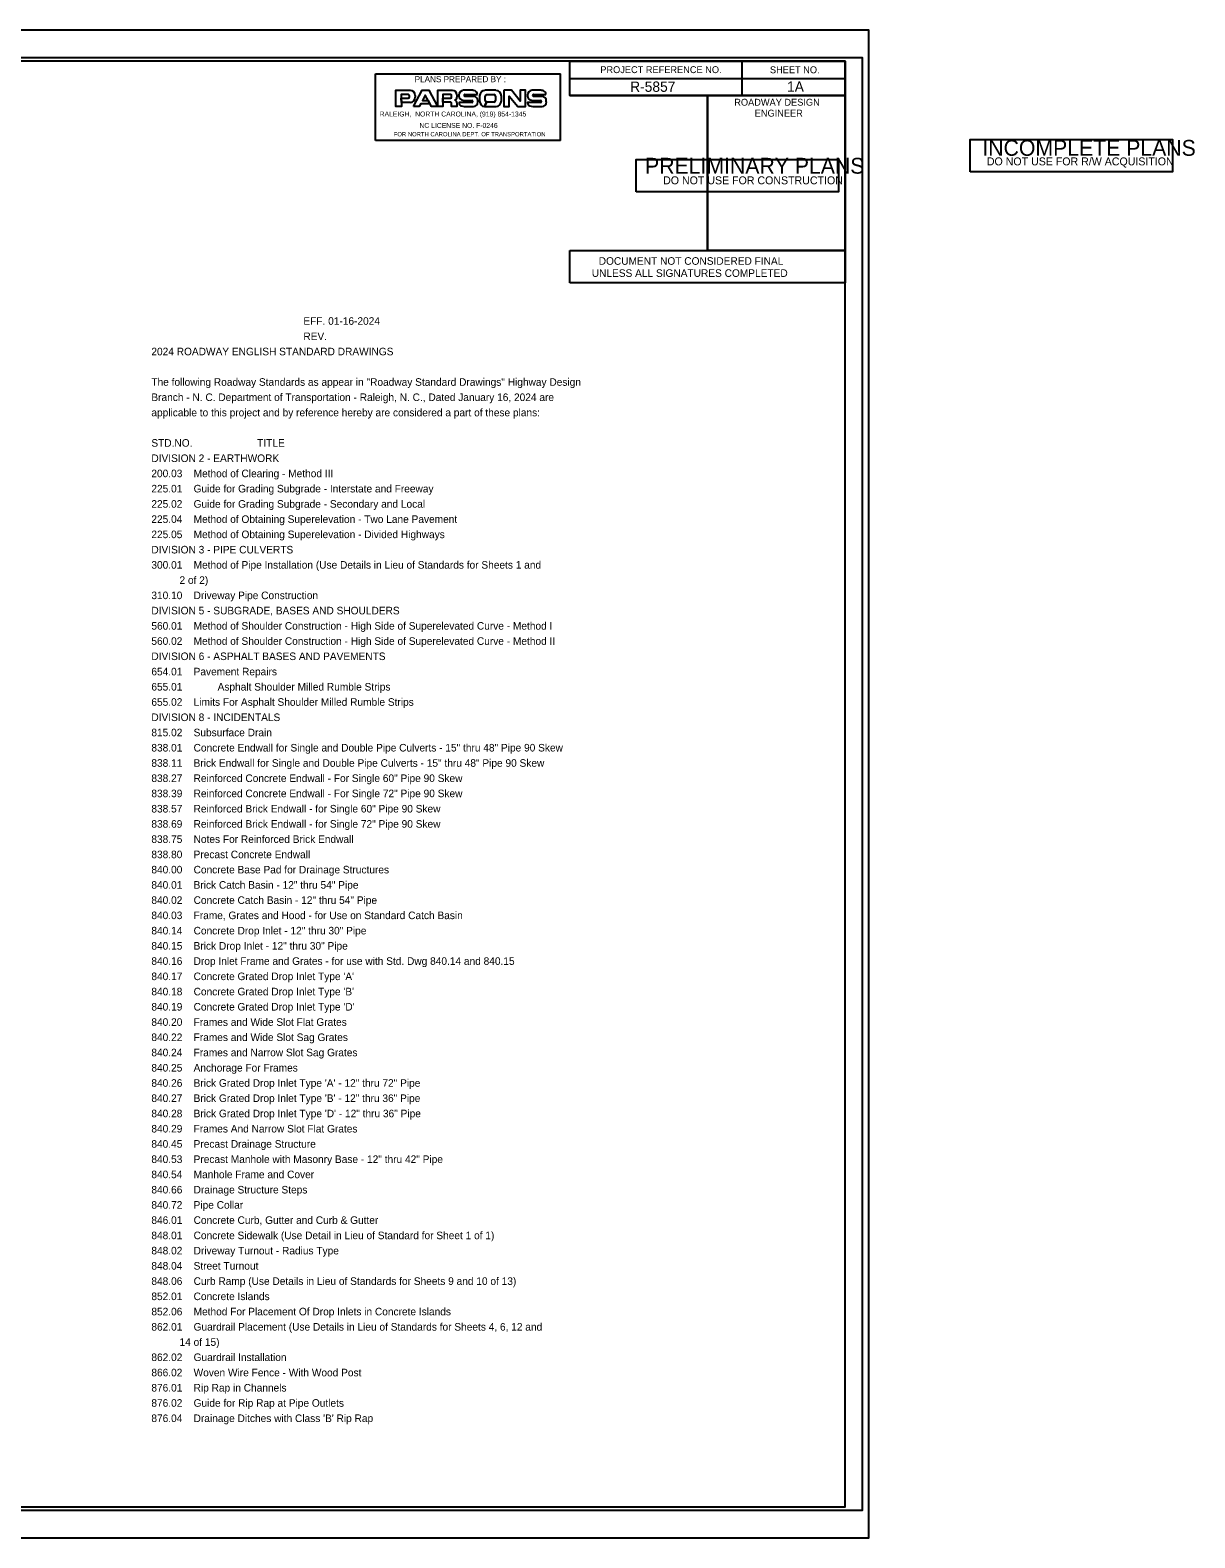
# Model space of a CAD drawing. Extents: x 779200 to 786346, y 600107 to 602297.
# Drawn here: x 782920 to 784611, y 600107 to 602297 of the extents above; entities that cross this region are included whole.
import ezdxf

# ---------------------------------------------------------------- set-up
doc = ezdxf.new("R2010")
doc.units = 0
for name, color, linetype in [('Old_Level_2', 7, 'Continuous'), ('Sheet Border Standard 30in CELL', 7, 'Continuous'), ('Sheet Cutting Line CELL', 7, 'Continuous'), ('Sheet Data Field CELL', 7, 'Continuous'), ('Sheet Plan CELL', 7, 'Continuous'), ('Sheet Plot Border Inside CELL', 7, 'Continuous'), ('Sheet Plot Border Outside CELL', 7, 'Continuous'), ('Sheet Sticker Exception Certification CELL', 7, 'Continuous'), ('Sheet Sticker Preliminary CELL', 7, 'Continuous')]:
    doc.layers.add(name, color=color, linetype=linetype)

msp = doc.modelspace()

# ---------------------------------------------------------------- linework, layer by layer
at = {"layer": 'Sheet Border Standard 30in CELL'}
for p, q in [((783953.3, 602251.6), (783953.3, 602201.6)), ((783703.2, 602226.6), (784103.3, 602226.6)), ((783703.2, 602201.6), (784103.3, 602201.6)), ((783703.2, 602201.6), (784103.3, 602201.6)), ((783903.3, 602201.6), (783903.3, 601976.7))]:
    msp.add_line(p, q, dxfattribs=at)
for points in [[(784103.3, 602251.7), (781103.3, 602251.7), (781103.3, 600151.7), (784103.3, 600151.7)], [(783703.2, 602251.7), (784103.3, 602251.7), (784103.3, 602201.6), (783703.2, 602201.6)], [(783903.3, 602201.6), (784103.3, 602201.6), (784103.3, 601976.6), (783903.3, 601976.6)]]:
    msp.add_lwpolyline(points, close=True, dxfattribs=at)
at = {"layer": 'Sheet Cutting Line CELL'}
msp.add_lwpolyline([(783799.6, 602061.9), (783799.6, 602108.9), (784093.6, 602108.9), (784093.6, 602061.9)], close=True, dxfattribs=at)
at = {"layer": 'Sheet Data Field CELL'}
msp.add_lwpolyline([(780770.3, 600106.7), (784137.3, 600106.7), (784137.3, 602296.7), (780770.3, 602296.7)], close=True, dxfattribs=at)
at = {"layer": 'Sheet Plan CELL'}
for p, q in [((783703.2, 601929.6), (783703.2, 601976.6)), ((783703.2, 601976.6), (784103.3, 601976.6)), ((784103.3, 601976.6), (784103.3, 601929.6)), ((784103.3, 601929.6), (783703.2, 601929.6))]:
    msp.add_line(p, q, dxfattribs=at)
at = {"layer": 'Sheet Plot Border Inside CELL'}
msp.add_lwpolyline([(780796.3, 600146.7), (784128.3, 600146.7), (784128.3, 602256.7), (780796.3, 602256.7)], close=True, dxfattribs=at)
at = {"layer": 'Sheet Plot Border Outside CELL'}
msp.add_lwpolyline([(784284.4, 602090.8), (784284.4, 602137.8), (784578.4, 602137.8), (784578.4, 602090.8)], close=True, dxfattribs=at)
at = {"layer": 'Sheet Sticker Exception Certification CELL'}
for p, q in [((783421.1, 602233.3), (783689.9, 602233.3)), ((783421.1, 602136.5), (783421.1, 602233.3)), ((783689.9, 602136.5), (783689.9, 602233.3)), ((783562.3, 602209.3), (783549, 602209.3)), ((783596.1, 602209.3), (783579.8, 602209.3)), ((783661.8, 602209.3), (783648.5, 602209.3)), ((783470.8, 602199.8), (783470.8, 602201.2)), ((783478.9, 602201.6), (783478.9, 602199.3)), ((783531.7, 602199.3), (783531.7, 602201.9)), ((783539.3, 602202.7), (783539.3, 602199.2)), ((783542.3, 602202.1), (783542.3, 602201.2)), ((783548.2, 602194.7), (783561.3, 602194.4)), ((783549.9, 602185.9), (783563.6, 602185.9)), ((783551.1, 602203.3), (783569.1, 602203.3)), ((783564, 602200.4), (783551.1, 602200.4)), ((783569.7, 602192.4), (783569.7, 602194.3)), ((783572.4, 602201.3), (783572.4, 602193.5)), ((783579.5, 602185.9), (783582.6, 602192.1)), ((783579.5, 602185.9), (783596.3, 602185.9)), ((783580.3, 602194.6), (783580.3, 602200.6)), ((783582.6, 602203), (783593.2, 602203)), ((783595.5, 602200.6), (783595.5, 602194.6)), ((783604, 602194.1), (783604, 602200.7)), ((783641.8, 602202.1), (783641.8, 602201.2)), ((783647.7, 602194.7), (783660.8, 602194.4)), ((783649.4, 602185.9), (783663.1, 602185.9)), ((783650.7, 602203.3), (783668.7, 602203.3)), ((783663.5, 602200.4), (783650.7, 602200.4)), ((783669.2, 602192.4), (783669.2, 602194.3)), ((783689.9, 602136.5), (783421.1, 602136.5))]:
    msp.add_line(p, q, dxfattribs=at)
for points in [[(783469, 602203), (783458.7, 602203), (783458.7, 602197.7), (783458.9, 602191.7), (783458.9, 602185.9), (783450.6, 602185.9), (783450.6, 602209.3), (783471.8, 602209.3)], [(783530.7, 602203), (783519.2, 602203), (783519.2, 602197.8), (783519.2, 602192.1), (783519.2, 602185.9), (783511.5, 602185.9), (783511.5, 602209.3), (783533.2, 602209.3)], [(783471.8, 602191.7), (783458.9, 602191.7), (783458.7, 602197.7), (783468.8, 602197.7)], [(783539.3, 602190.9), (783539.3, 602185.9), (783531.5, 602185.9), (783531.5, 602191.2), (783530.5, 602192.1), (783519.2, 602192.1), (783519.2, 602197.8), (783530.3, 602197.8)], [(783561.3, 602191.5), (783542.6, 602191.5), (783542.6, 602191.1)], [(783593.2, 602192.1), (783582.6, 602192.1), (783579.5, 602185.9), (783596.3, 602185.9)], [(783660.8, 602191.5), (783642.1, 602191.5), (783642.1, 602191.1)]]:
    msp.add_lwpolyline(points, dxfattribs=at)
for points in [[(783476.2, 602185.9), (783489.1, 602209.3), (783498.5, 602209.3), (783511.2, 602185.9), (783502.4, 602185.9), (783493.5, 602202.2), (783489.4, 602194.7), (783497.6, 602194.7), (783500.3, 602189.9), (783486.9, 602189.9), (783484.7, 602185.9)], [(783607.6, 602209.3), (783607.6, 602185.9), (783615.5, 602185.9), (783615.5, 602201), (783627.7, 602185.9), (783638.8, 602185.9), (783638.8, 602209.3), (783631.2, 602209.3), (783631.2, 602193.7), (783618.9, 602209.3)]]:
    msp.add_lwpolyline(points, close=True, dxfattribs=at)
for centre, major_axis, ratio, start_param, end_param in [((783471.8, 602201.6), (0, 7.65), 0.93676, 4.712389, 6.283185), ((783533.2, 602202.7), (0, 6.58), 0.934072, 4.712389, 6.283185), ((783549, 602202.1), (0, 7.19), 0.934072, 0, 1.570796), ((783562.3, 602199.3), (0, 9.94), 0.934072, 5.902203, 6.283185), ((783563.7, 602203.2), (0, 5.82), 0.934072, 4.738699, 5.901866), ((783579.8, 602201.3), (0, 7.96), 0.924824, 0, 1.570796), ((783596.1, 602200.7), (0, 8.57), 0.924824, 4.712389, 6.283185), ((783648.5, 602202.1), (0, 7.19), 0.934072, 0, 1.570796), ((783661.8, 602199.3), (0, 9.94), 0.934072, 5.902203, 6.283185), ((783663.2, 602203.2), (0, 5.82), 0.934072, 4.738699, 5.901866), ((783468.8, 602199.8), (0, 2.14), 0.93676, 3.141593, 4.712389), ((783469, 602201.2), (0, 1.84), 0.93676, 4.712389, 6.283185), ((783471.8, 602199.3), (0, 7.65), 0.93676, 3.141593, 4.712389), ((783530.3, 602199.3), (0, 1.53), 0.934072, 3.141593, 4.712389), ((783530.7, 602201.9), (0, 1.07), 0.934072, 4.712389, 6.283185), ((783535.6, 602199.2), (0, 3.98), 0.934072, 3.34512, 4.712389), ((783535, 602190.9), (0, 4.59), 0.934072, 4.712389, 5.969561), ((783548.3, 602201.2), (0, -6.43), 0.934072, 4.712389, 6.260753), ((783547, 602191.1), (0, -4.74), 0.934072, 4.712389, 5.988639), ((783549.9, 602201.2), (0, 15.3), 0.934072, 2.847261, 3.141593), ((783551.1, 602201.9), (0, 1.45), 0.934072, 0, 3.141593), ((783561.3, 602193), (0, 1.45), 0.934072, 3.141593, 6.283185), ((783563.6, 602192.4), (0, 6.58), 0.934072, 3.141593, 4.712389), ((783564, 602194.3), (0, 6.12), 0.934072, 4.712389, 6.283185), ((783579.5, 602193.5), (0, -7.65), 0.924824, 4.712389, 6.283185), ((783582.6, 602200.6), (0, -2.45), 0.924824, 3.141593, 4.712389), ((783582.6, 602194.6), (0, -2.45), 0.924824, 4.712389, 6.283185), ((783593.2, 602200.6), (0, 2.45), 0.924824, 4.712389, 6.283185), ((783593.2, 602194.6), (0, 2.45), 0.924824, 3.141593, 4.712389), ((783596.3, 602194.1), (0, 8.26), 0.924824, 3.141593, 4.712389), ((783647.8, 602201.2), (0, -6.43), 0.934072, 4.712389, 6.260753), ((783646.5, 602191.1), (0, -4.74), 0.934072, 4.712389, 5.988639), ((783649.4, 602201.2), (0, 15.3), 0.934072, 2.847261, 3.141593), ((783650.7, 602201.9), (0, 1.45), 0.934072, 0, 3.141593), ((783660.8, 602193), (0, 1.45), 0.934072, 3.141593, 6.283185), ((783663.1, 602192.4), (0, 6.58), 0.934072, 3.141593, 4.712389), ((783663.5, 602194.3), (0, 6.12), 0.934072, 4.712389, 6.283185)]:
    msp.add_ellipse(centre, major_axis=major_axis, ratio=ratio, start_param=start_param, end_param=end_param, dxfattribs=at)

# ---------------------------------------------------------------- texts
at = {"layer": 'Old_Level_2'}
for s, p in [('R-5857', (783790.9, 602207.1)), ('1A', (784018.7, 602207.2))]:
    msp.add_text(s, height=15, dxfattribs=at).set_placement(p)
at = {"layer": 'Sheet Border Standard 30in CELL'}
for s, p in [('PROJECT REFERENCE NO.', (783747.6, 602234.3)), ('SHEET NO.', (783993.9, 602234.1)), ('ROADWAY DESIGN', (783942.1, 602187)), ('ENGINEER', (783971.8, 602171.1))]:
    msp.add_text(s, height=10, dxfattribs=at).set_placement(p)
at = {"layer": 'Sheet Cutting Line CELL'}
for s, height, p in [('PRELIMINARY PLANS', 23.04, (783812.6, 602088.2)), ('DO NOT USE FOR CONSTRUCTION', 11.52, (783838.8, 602072.8))]:
    msp.add_text(s, height=height, dxfattribs=at).set_placement(p)
at = {"layer": 'Sheet Plan CELL'}
for s, p in [('DOCUMENT NOT CONSIDERED FINAL', (783745.3, 601955.9)), ('UNLESS ALL SIGNATURES COMPLETED', (783735.2, 601938.3))]:
    msp.add_text(s, height=11, dxfattribs=at).set_placement(p)
at = {"layer": 'Sheet Plot Border Outside CELL'}
for s, height, p in [('INCOMPLETE PLANS', 23.04, (784302.3, 602114.2)), ('DO NOT USE FOR R/W ACQUISITION', 11.52, (784308.8, 602100.3))]:
    msp.add_text(s, height=height, dxfattribs=at).set_placement(p)
at = {"layer": 'Sheet Sticker Exception Certification CELL'}
for s, height, rotation, p in [('PLANS PREPARED BY : ', 8.829, 359.999, (783478.1, 602221.1)), ('RALEIGH,  NORTH CAROLINA, (919) 854-1345', 7.151, 360, (783427.2, 602171.3)), ('FOR NORTH CAROLINA DEPT. OF TRANSPORTATION', 6.203, 359.9999, (783447.7, 602142.5)), ('NC LICENSE NO. F-0246', 7.151, 360, (783485, 602154.7))]:
    msp.add_text(s, height=height, rotation=rotation, dxfattribs=at).set_placement(p)
at = {"layer": 'Sheet Sticker Preliminary CELL'}
for s, p in [('                                                      EFF. 01-16-2024', (783095.8, 601868.7)), ('                                                      REV. ', (783095.8, 601846.5)), ('2024 ROADWAY ENGLISH STANDARD DRAWINGS', (783095.8, 601824.4)), ('The following Roadway Standards as appear in "Roadway Standard Drawings" Highway Design', (783095.8, 601780.1)), ('Branch - N. C. Department of Transportation - Raleigh, N. C., Dated January 16, 2024 are', (783095.8, 601758)), ('applicable to this project and by reference hereby are considered a part of these plans:', (783095.8, 601735.8)), ('STD.NO.                       TITLE', (783095.8, 601691.6)), ('200.03    Method of Clearing - Method III', (783095.8, 601647.3)), ('DIVISION 2 - EARTHWORK', (783095.8, 601669.4)), ('225.01    Guide for Grading Subgrade - Interstate and Freeway', (783095.8, 601625.2)), ('225.02    Guide for Grading Subgrade - Secondary and Local', (783095.8, 601603)), ('225.04    Method of Obtaining Superelevation - Two Lane Pavement', (783095.8, 601580.9)), ('225.05    Method of Obtaining Superelevation - Divided Highways', (783095.8, 601558.8)), ('DIVISION 3 - PIPE CULVERTS', (783095.8, 601536.6)), ('300.01    Method of Pipe Installation (Use Details in Lieu of Standards for Sheets 1 and', (783095.8, 601514.5)), ('          2 of 2)', (783095.8, 601492.4)), ('310.10    Driveway Pipe Construction', (783095.8, 601470.2)), ('DIVISION 5 - SUBGRADE, BASES AND SHOULDERS', (783095.8, 601448.1)), ('560.01    Method of Shoulder Construction - High Side of Superelevated Curve - Method I', (783095.8, 601425.9)), ('560.02    Method of Shoulder Construction - High Side of Superelevated Curve - Method II', (783095.8, 601403.8)), ('DIVISION 6 - ASPHALT BASES AND PAVEMENTS', (783095.8, 601381.7)), ('654.01    Pavement Repairs', (783095.8, 601359.5)), ('655.01', (783095.8, 601337.4)), ('  Asphalt Shoulder Milled Rumble Strips', (783183.8, 601337.4)), ('655.02    Limits For Asphalt Shoulder Milled Rumble Strips', (783095.8, 601315.3)), ('DIVISION 8 - INCIDENTALS', (783095.8, 601293.1)), ('815.02    Subsurface Drain', (783095.8, 601271)), ('838.01    Concrete Endwall for Single and Double Pipe Culverts - 15" thru 48" Pipe 90 Skew', (783095.8, 601248.9)), ('838.11    Brick Endwall for Single and Double Pipe Culverts - 15" thru 48" Pipe 90 Skew', (783095.8, 601226.7)), ('838.27    Reinforced Concrete Endwall - For Single 60" Pipe 90 Skew', (783095.8, 601204.6)), ('838.39    Reinforced Concrete Endwall - For Single 72" Pipe 90 Skew', (783095.8, 601182.5)), ('838.57    Reinforced Brick Endwall - for Single 60" Pipe 90 Skew', (783095.8, 601160.3)), ('838.69    Reinforced Brick Endwall - for Single 72" Pipe 90 Skew', (783095.8, 601138.2)), ('838.75    Notes For Reinforced Brick Endwall', (783095.8, 601116.1)), ('838.80    Precast Concrete Endwall', (783095.8, 601093.9)), ('840.00    Concrete Base Pad for Drainage Structures', (783095.8, 601071.8)), ('840.01    Brick Catch Basin - 12" thru 54" Pipe', (783095.8, 601049.6)), ('840.02    Concrete Catch Basin - 12" thru 54" Pipe', (783095.8, 601027.5)), ('840.03    Frame, Grates and Hood - for Use on Standard Catch Basin', (783095.8, 601005.4)), ('840.14    Concrete Drop Inlet - 12" thru 30" Pipe', (783095.8, 600983.2)), ('840.15    Brick Drop Inlet - 12" thru 30" Pipe', (783095.8, 600961.1)), ('840.16    Drop Inlet Frame and Grates - for use with Std. Dwg 840.14 and 840.15', (783095.8, 600939)), ("840.17    Concrete Grated Drop Inlet Type 'A'", (783095.8, 600916.8)), ("840.18    Concrete Grated Drop Inlet Type 'B'", (783095.8, 600894.7)), ("840.19    Concrete Grated Drop Inlet Type 'D'", (783095.8, 600872.6)), ('840.20    Frames and Wide Slot Flat Grates', (783095.8, 600850.4)), ('840.22    Frames and Wide Slot Sag Grates', (783095.8, 600828.3)), ('840.24    Frames and Narrow Slot Sag Grates', (783095.8, 600806.2)), ('840.25    Anchorage For Frames', (783095.8, 600784)), ('840.26    Brick Grated Drop Inlet Type \'A\' - 12" thru 72" Pipe', (783095.8, 600761.9)), ('840.27    Brick Grated Drop Inlet Type \'B\' - 12" thru 36" Pipe', (783095.8, 600739.8)), ('840.28    Brick Grated Drop Inlet Type \'D\' - 12" thru 36" Pipe', (783095.8, 600717.6)), ('840.29    Frames And Narrow Slot Flat Grates', (783095.8, 600695.5)), ('840.45    Precast Drainage Structure', (783095.8, 600673.4)), ('840.53    Precast Manhole with Masonry Base - 12" thru 42" Pipe', (783095.8, 600651.2)), ('840.54    Manhole Frame and Cover', (783095.8, 600629.1)), ('840.66    Drainage Structure Steps', (783095.8, 600606.9)), ('840.72    Pipe Collar', (783095.8, 600584.8)), ('846.01    Concrete Curb, Gutter and Curb & Gutter', (783095.8, 600562.7)), ('848.01    Concrete Sidewalk (Use Detail in Lieu of Standard for Sheet 1 of 1)', (783095.8, 600540.5)), ('848.02    Driveway Turnout - Radius Type', (783095.8, 600518.4)), ('848.04    Street Turnout', (783095.8, 600496.3)), ('848.06    Curb Ramp (Use Details in Lieu of Standards for Sheets 9 and 10 of 13)', (783095.8, 600474.1)), ('852.01    Concrete Islands', (783095.8, 600452)), ('852.06    Method For Placement Of Drop Inlets in Concrete Islands', (783095.8, 600429.9)), ('862.01    Guardrail Placement (Use Details in Lieu of Standards for Sheets 4, 6, 12 and', (783095.8, 600407.7)), ('          14 of 15)', (783095.8, 600385.6)), ('862.02    Guardrail Installation', (783095.8, 600363.5)), ('866.02    Woven Wire Fence - With Wood Post', (783095.8, 600341.3)), ('876.01    Rip Rap in Channels', (783095.8, 600319.2)), ('876.02    Guide for Rip Rap at Pipe Outlets', (783095.8, 600297.1)), ("876.04    Drainage Ditches with Class 'B' Rip Rap", (783095.8, 600274.9))]:
    msp.add_text(s, height=11, dxfattribs=at).set_placement(p)

doc.saveas('drawing.dxf')
